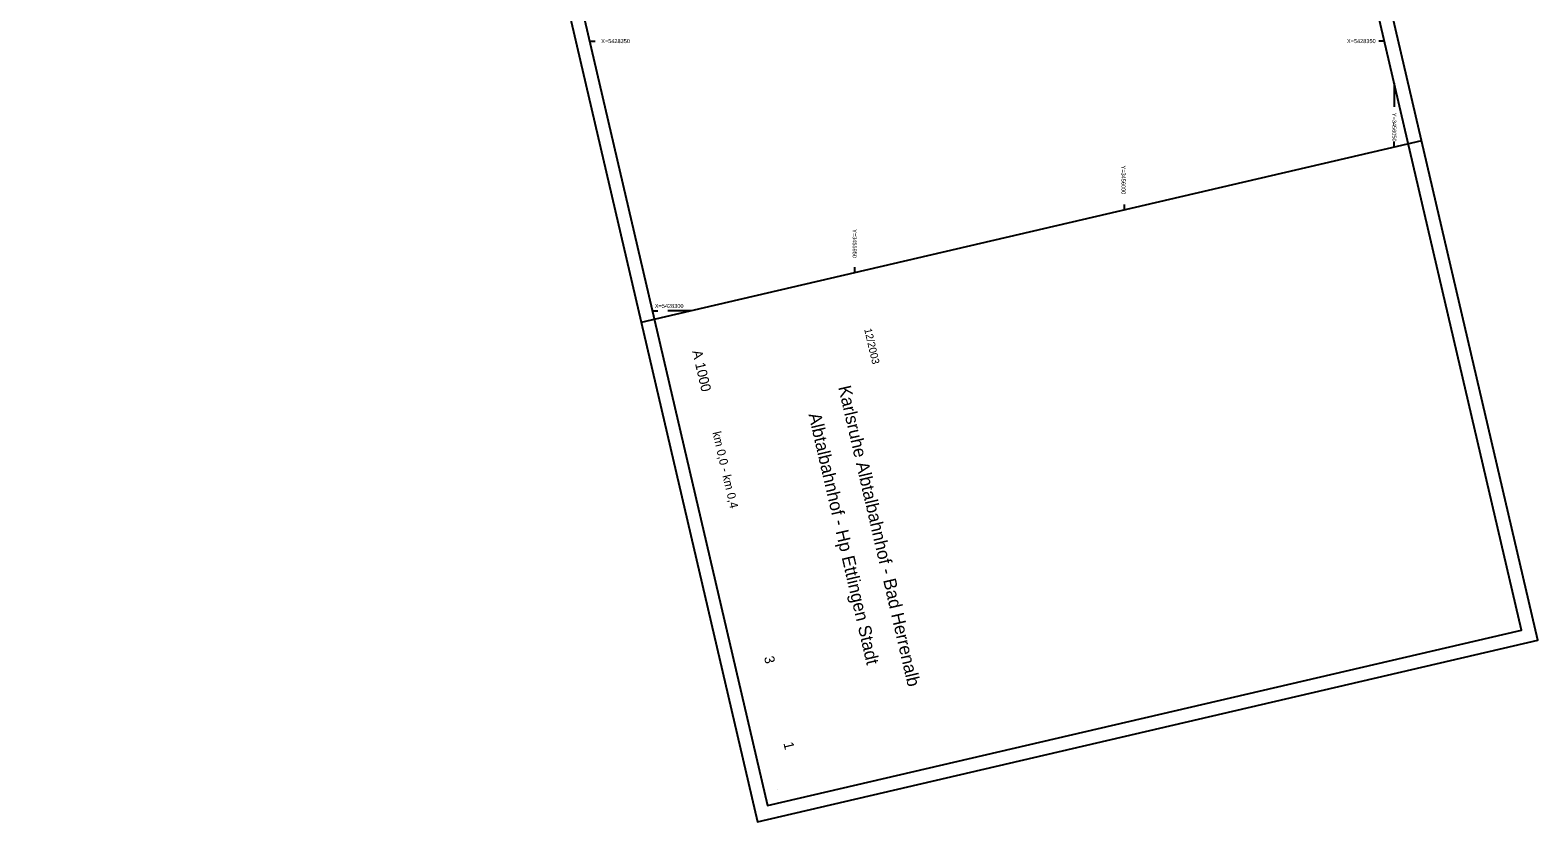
# Model space of a CAD drawing. Extents: x 3455797 to 3456077, y 5428205 to 5428818.
# Drawn here: x 3455797.2 to 3456076.6, y 5428205.3 to 5428352 of the extents above; entities that cross this region are included whole.
import ezdxf

# ---------------------------------------------------------------- set-up
doc = ezdxf.new("R2010")
doc.units = 0
for name, color, linetype in [('_GINETZ', 7, 'Continuous'), ('PK_BEREICH', 7, 'Continuous'), ('PK_BESCHRIFT', 7, 'Continuous'), ('PK_Strecke', 7, 'Continuous'), ('Planrahmen', 7, 'Continuous')]:
    doc.layers.add(name, color=color, linetype=linetype)

msp = doc.modelspace()

# ---------------------------------------------------------------- linework, layer by layer
at = {"layer": '_GINETZ'}
for p, q in [((3455900.85, 5428350), (3455901.88, 5428350)), ((3456048.19, 5428350), (3456047.16, 5428350)), ((3456050, 5428342.23), (3456050, 5428337.82)), ((3456050, 5428330.32), (3456050, 5428331.35)), ((3456000, 5428318.68), (3456000, 5428319.71)), ((3455950, 5428307.04), (3455950, 5428308.07)), ((3455912.49, 5428300), (3455913.52, 5428300)), ((3455919.76, 5428300), (3455915.35, 5428300))]:
    msp.add_line(p, q, dxfattribs=at)
at = {"layer": 'Planrahmen'}
for p, q in [((3456055.07, 5428331.5), (3455910.43, 5428297.83)), ((3455935.71, 5428211.31), (3455935.71, 5428211.31))]:
    msp.add_line(p, q, dxfattribs=at)
for points in [[(3455797.16, 5428784.32), (3455931.98, 5428205.3), (3456076.61, 5428238.98), (3455941.8, 5428817.99)], [(3455801.86, 5428775.14), (3455933.84, 5428208.31), (3456073.61, 5428240.85), (3455941.63, 5428807.69)]]:
    msp.add_lwpolyline(points, close=True, dxfattribs=at)

# ---------------------------------------------------------------- texts
at = {"layer": '_GINETZ'}
for s, p in [('X=5428350', (3455903, 5428349.62)), ('X=5428350', (3456041.22, 5428349.62)), ('X=5428300', (3455912.94, 5428300.53))]:
    msp.add_text(s, height=0.75, dxfattribs=at).set_placement(p)
for s, p in [('Y=3456050', (3456049.62, 5428336.7)), ('Y=3456000', (3455999.44, 5428326.94)), ('Y=3455950', (3455949.62, 5428315.14))]:
    msp.add_text(s, height=0.75, rotation=270, dxfattribs=at).set_placement(p)
at = {"layer": 'PK_BEREICH'}
msp.add_text('Albtalbahnhof - Hp Ettlingen Stadt', height=2.3732, rotation=283.1068, dxfattribs=at).set_placement((3455941.4, 5428280.8))
at = {"layer": 'PK_BESCHRIFT'}
for s, height, p in [('12/2003', 1.4, (3455951.74, 5428296.6)), ('A 1000', 1.846, (3455919.86, 5428292.5)), ('km 0,0 - km 0,4', 1.5821, (3455923.61, 5428277.46)), ('3', 1.85, (3455933.17, 5428235.81)), ('1', 1.85, (3455936.77, 5428219.89))]:
    msp.add_text(s, height=height, rotation=283.1068, dxfattribs=at).set_placement(p)
at = {"layer": 'PK_Strecke'}
msp.add_text('Karlsruhe Albtalbahnhof - Bad Herrenalb', height=2.3732, rotation=283.1068, dxfattribs=at).set_placement((3455946.92, 5428285.86))

doc.saveas('drawing.dxf')
